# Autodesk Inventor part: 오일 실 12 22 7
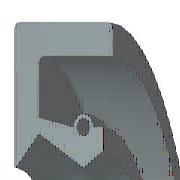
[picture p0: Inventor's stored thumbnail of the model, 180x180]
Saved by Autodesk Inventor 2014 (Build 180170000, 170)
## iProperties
IsCustomPart: 1
Created: 2012-02
Part Number: 오일 실 12 22 7
Material: 고무
Description: 오일-실
Document SubType Name: Modeling
Standard: KS B 2804
Designer: mduedu
Standards Organization: KS
Language: ko-KR
Size Designation: D - 12 22 7
Categories: <MemberInstance><Categories><Category DisplayName="샤프트 부품" InternalName="7f7aeb1f-a693-4053-b835-cee3144e0d98" Mnemonic="SHFT"><Category DisplayName="실링" Intern
Density: 0.93 g/cm^3
Mass: 1.25383 g
Surface Area: 18.4996 cm^2
Volume: 1.3482 cm^3
Appearance: Rubber - Black - Version 1.1
Author: mduedu
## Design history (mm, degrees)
revolve "본체" stored, may be unused: angle "d17" = 90 deg
revolve "스프링1" stored, may be unused: angle "d18" = 90 deg
body "Solid1"
sketch "스케치1"
  geometry: L1 (0, 11)-(7, 11); L2 (7, 9.25)-(1.75, 9.25); L3 (1.75, 7.75)-(4.9, 6); L4 (4.9, 6)-(0, 6); L5 (0, 0)-(9.586, 0) reference; L6 (4.9, 6)-(6.3, 6.875); L7 (0, 18)-(0, -3) reference; L8 (-1.941, 0)-(11.507, 0) reference; L9 (4.2, 8.1)-(1.75, 8.59); L10 (1.75, 8.59)-(1.75, 9.25); L11 (0, 11)-(0, 6.088); L12 (4.9, 6)-(0, 6); L13 (1.75, 7.75)-(0.152, 6.028); L14 (7, 11)-(7, 9.25); L15 (5.6, 8.1)-(6.3, 8.1); L16 (6.3, 8.1)-(6.3, 6.875); C1 r 0.455 at (4.9, 8.1); A1 r 0.7 centre (4.9, 8.1) between (5.6, 8.1) and (4.2, 8.1); A2 r 0.088 centre (0.088, 6.088) between (0, 6.088) and (0.152, 6.028); 1 further point
  constraints: 28 end point, 5 horizontal alignment, 5 point on line, 4 point on circle, 4 vertical alignment, 3 centre point, 3 tangent, 2 collinear, 2 horizontal, 2 perpendicular, 1 coincident, 1 parallel
  dimensions: "d0" = 22 diameter of L1 L5 (= SD2); "d1" = 1.75 distance of L1.end L2.start (= SD); "d2" = 0.91 diameter of C1 (= SPDI); "d3" = 1.4 diameter of A1 (= SPDA); "d4" = 12 diameter of L3.end L5 (= NND); "d5" = 15.5 diameter of L3.start L5 (= TKDM); "d7" = 17.18 diameter of L9.end L5 (= TKDM + 0.24 x SWDT); "d8" = 1.75 distance between parallel lines of L11 L10 (= SD); "d9" = 4.9 distance from line of L11 C1.centre (= SPDST); "d10" = 16.2 diameter of C1.centre L5 (= HLDM); "d11" = 0.0875 radius of A2 (= 0.25 x LAB); "d12" = 6.3 distance between parallel lines of L11 L16 (= SDI); "d13" = 13.75 diameter of L6.end L5 (= ABDM); "d14" = 7 distance from line of L11 L1.end (= SWDT)
fillet "모깎기1" dims "d6" = 0.3 (= RR)
other parameters: "SD2" = 22 [user parameter; used in 1 equation term], "SWDT" = 7 [user parameter; used in 2 equation terms], "RR" = 0.3 [user parameter; used in 1 equation term], "SD" = 1.75 [user parameter; used in 2 equation terms], "NND" = 12 [user parameter; used in 1 equation term], "SPDA" = 1.4 [user parameter; used in 1 equation term], "SPDI" = 0.91 [user parameter; used in 1 equation term], "TKDM" = 15.5 [user parameter; used in 2 equation terms], "HLDM" = 16.2 [user parameter; used in 1 equation term], "ABDM" = 13.75 [user parameter; used in 1 equation term], "SDI" = 6.3 [user parameter; used in 1 equation term], "SPDST" = 4.9 [user parameter; used in 1 equation term], "LAB" = 0.35 [user parameter; used in 1 equation term], "d15" = 0, "d16" = 0, "d19" = 0
